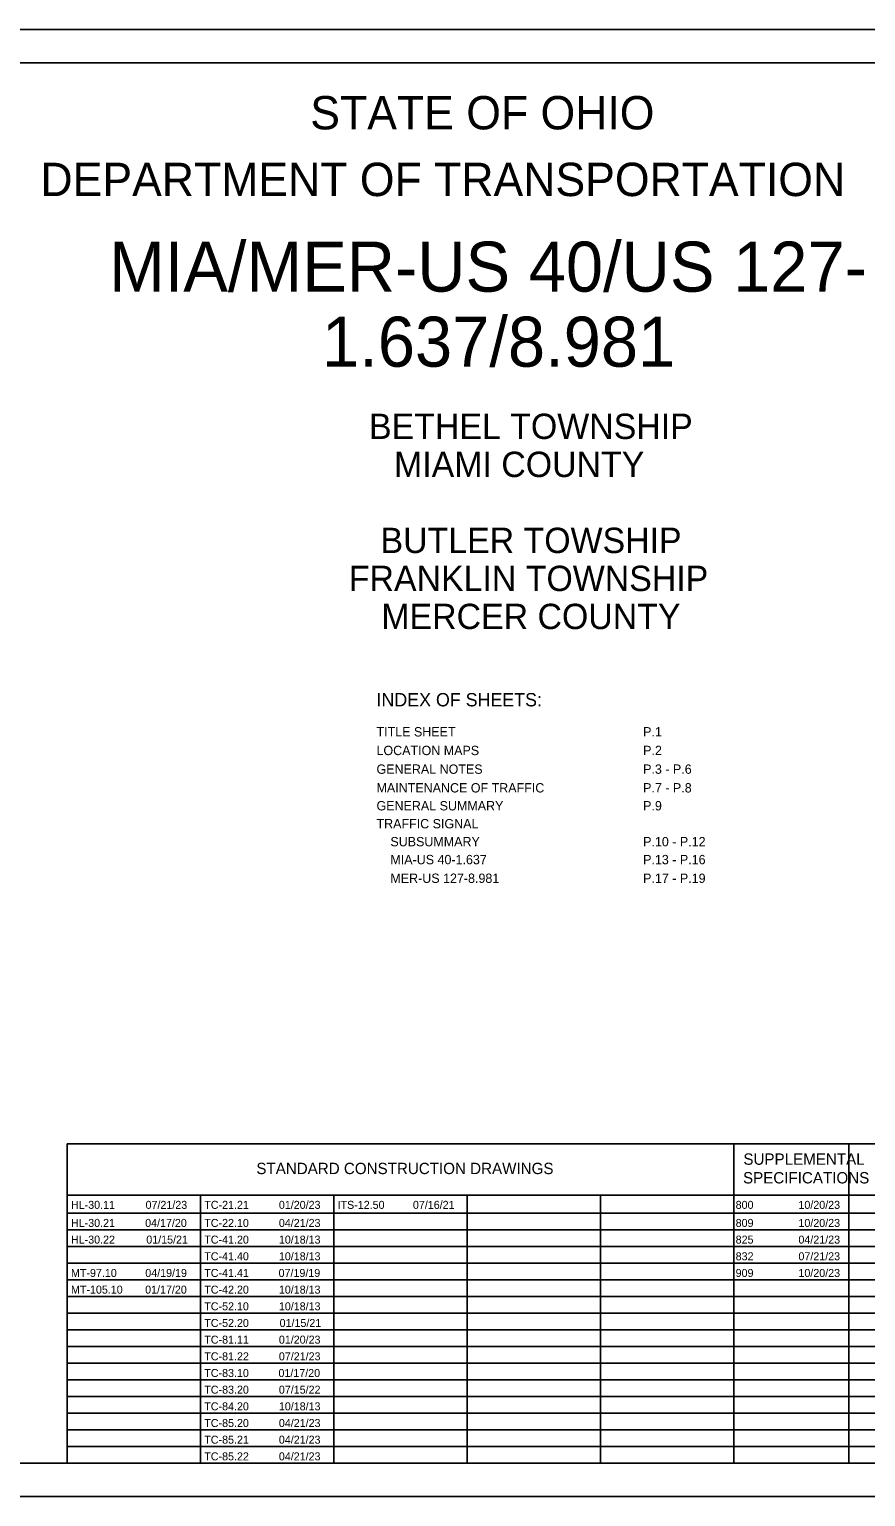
# Model space of a CAD drawing. Extents: x 0 to 34, y 0 to 22.
# Drawn here: x 9.58 to 22.13, y 0 to 22 of the extents above; entities that cross this region are included whole.
import ezdxf

# ---------------------------------------------------------------- set-up
doc = ezdxf.new("R2010")
doc.units = 0
for name, color, linetype in [('SH_Border', 7, 'Continuous'), ('SH_Cut_Line', 7, 'Continuous'), ('SH_Data', 7, 'Continuous'), ('SH_Text', 7, 'Continuous')]:
    doc.layers.add(name, color=color, linetype=linetype)

msp = doc.modelspace()

# ---------------------------------------------------------------- linework, layer by layer
at = {"layer": 'SH_Border'}
msp.add_lwpolyline([(1.5, 21.5), (33.5, 21.5), (33.5, 0.5), (1.5, 0.5)], close=True, dxfattribs=at)
at = {"layer": 'SH_Cut_Line'}
msp.add_lwpolyline([(0, 0), (34, 0), (34, 22), (0, 22)], close=True, dxfattribs=at)
at = {"layer": 'SH_Data'}
for p, q in [((10.15, 5.292), (23.6, 5.292)), ((10.15, 0.5), (10.15, 5.292)), ((20.15, 0.5), (20.15, 5.292)), ((21.875, 0.5), (21.875, 5.292)), ((10.15, 4.521), (23.6, 4.521)), ((12.15, 0.5), (12.15, 4.521)), ((14.15, 0.5), (14.15, 4.521)), ((16.15, 0.5), (16.15, 4.521)), ((18.15, 0.5), (18.15, 4.521)), ((10.15, 4.25), (23.6, 4.25)), ((10.15, 4), (23.6, 4)), ((10.15, 3.75), (23.6, 3.75)), ((10.15, 3.5), (23.6, 3.5)), ((10.15, 3.25), (23.6, 3.25)), ((10.15, 3), (23.6, 3)), ((10.15, 2.75), (23.6, 2.75)), ((10.15, 2.5), (23.6, 2.5)), ((10.15, 2.25), (23.6, 2.25)), ((10.15, 2), (23.6, 2)), ((10.15, 1.75), (23.6, 1.75)), ((10.15, 1.5), (23.6, 1.5)), ((10.15, 1.25), (23.6, 1.25)), ((10.15, 1), (23.6, 1)), ((10.15, 0.75), (23.6, 0.75))]:
    msp.add_line(p, q, dxfattribs=at)

# ---------------------------------------------------------------- texts
at = {"layer": 'SH_Text'}
for s, height, p in [('STATE OF OHIO', 0.5, (13.795, 20.5)), ('DEPARTMENT OF TRANSPORTATION', 0.5, (9.747, 19.5)), ('MIA/MER-US 40/US 127-', 0.75, (10.776, 18.067)), ('1.637/8.981', 0.75, (13.972, 16.942)), ('BETHEL TOWNSHIP', 0.38, (14.677, 15.858)), ('MIAMI COUNTY', 0.38, (15.052, 15.288)), ('BUTLER TOWSHIP', 0.38, (14.849, 14.148)), ('FRANKLIN TOWNSHIP', 0.38, (14.374, 13.578)), ('MERCER COUNTY', 0.38, (14.861, 13.008)), ('INDEX OF SHEETS:', 0.2, (14.789, 11.849)), ('TITLE SHEET', 0.14, (14.789, 11.398)), ('P.1', 0.14, (18.789, 11.398)), ('LOCATION MAPS', 0.14, (14.789, 11.118)), ('P.2', 0.14, (18.789, 11.118)), ('GENERAL NOTES', 0.14, (14.789, 10.838)), ('P.3 - P.6', 0.14, (18.789, 10.838)), ('MAINTENANCE OF TRAFFIC ', 0.14, (14.789, 10.558)), ('P.7 - P.8', 0.14, (18.789, 10.558)), ('GENERAL SUMMARY', 0.14, (14.789, 10.289)), ('P.9', 0.14, (18.789, 10.289)), ('TRAFFIC SIGNAL', 0.14, (14.789, 10.02)), ('    SUBSUMMARY', 0.14, (14.789, 9.751)), ('P.10 - P.12', 0.14, (18.789, 9.751)), ('    MIA-US 40-1.637', 0.14, (14.789, 9.482)), ('P.13 - P.16', 0.14, (18.789, 9.482)), ('    MER-US 127-8.981', 0.14, (14.789, 9.202)), ('P.17 - P.19', 0.14, (18.789, 9.202)), ('SUPPLEMENTAL', 0.17, (20.293, 4.976)), ('STANDARD CONSTRUCTION DRAWINGS', 0.17, (12.986, 4.836)), ('SPECIFICATIONS', 0.17, (20.287, 4.696)), ('HL-30.11', 0.12, (10.205, 4.315)), ('07/21/23', 0.12, (11.324, 4.315)), ('TC-21.21', 0.12, (12.205, 4.315)), ('01/20/23', 0.12, (13.324, 4.315)), ('ITS-12.50', 0.12, (14.205, 4.315)), ('07/16/21', 0.12, (15.335, 4.315)), ('800', 0.12, (20.177, 4.315)), ('10/20/23', 0.12, (21.119, 4.315)), ('HL-30.21', 0.12, (10.205, 4.044)), ('04/17/20', 0.12, (11.318, 4.044)), ('TC-22.10', 0.12, (12.205, 4.044)), ('04/21/23', 0.12, (13.324, 4.044)), ('809', 0.12, (20.177, 4.044)), ('10/20/23', 0.12, (21.119, 4.044)), ('HL-30.22', 0.12, (10.205, 3.794)), ('01/15/21', 0.12, (11.335, 3.794)), ('TC-41.20', 0.12, (12.205, 3.794)), ('10/18/13', 0.12, (13.324, 3.794)), ('825', 0.12, (20.177, 3.794)), ('04/21/23', 0.12, (21.119, 3.794)), ('TC-41.40', 0.12, (12.205, 3.544)), ('10/18/13', 0.12, (13.324, 3.544)), ('832', 0.12, (20.177, 3.544)), ('07/21/23', 0.12, (21.119, 3.544)), ('MT-97.10', 0.12, (10.205, 3.294)), ('04/19/19', 0.12, (11.32, 3.294)), ('TC-41.41', 0.12, (12.205, 3.294)), ('07/19/19', 0.12, (13.32, 3.294)), ('909', 0.12, (20.177, 3.294)), ('10/20/23', 0.12, (21.119, 3.294)), ('MT-105.10', 0.12, (10.205, 3.044)), ('01/17/20', 0.12, (11.318, 3.044)), ('TC-42.20', 0.12, (12.205, 3.044)), ('10/18/13', 0.12, (13.324, 3.044)), ('TC-52.10', 0.12, (12.205, 2.794)), ('10/18/13', 0.12, (13.324, 2.794)), ('TC-52.20', 0.12, (12.205, 2.544)), ('01/15/21', 0.12, (13.335, 2.544)), ('01/20/23', 0.12, (13.324, 2.294)), ('TC-81.11', 0.12, (12.205, 2.294)), ('TC-81.22', 0.12, (12.205, 2.044)), ('07/21/23', 0.12, (13.324, 2.044)), ('TC-83.10', 0.12, (12.205, 1.794)), ('01/17/20', 0.12, (13.318, 1.794)), ('TC-83.20', 0.12, (12.205, 1.544)), ('07/15/22', 0.12, (13.324, 1.544)), ('TC-84.20', 0.12, (12.205, 1.294)), ('10/18/13', 0.12, (13.324, 1.294)), ('TC-85.20', 0.12, (12.205, 1.044)), ('04/21/23', 0.12, (13.324, 1.044)), ('TC-85.21', 0.12, (12.205, 0.794)), ('04/21/23', 0.12, (13.324, 0.794)), ('TC-85.22', 0.12, (12.205, 0.544)), ('04/21/23', 0.12, (13.324, 0.544))]:
    msp.add_text(s, height=height, dxfattribs=at).set_placement(p)

doc.saveas('drawing.dxf')
